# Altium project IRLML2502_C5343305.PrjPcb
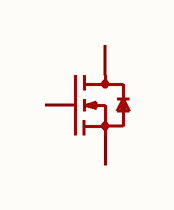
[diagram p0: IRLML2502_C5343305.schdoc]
1 sheet, 1 parts. Net scope: global (net labels, ports and power ports of the same name join across sheets).

## Sheet IRLML2502_C5343305.schdoc
size 127 x 101 mm

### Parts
Q?  irlml2502_c5343305  [SOT-23-3_L2.9-W1.3-P1.90-LS2.4-BR]  (value not drawn)

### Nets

Not connected (* = marked no-connect by the designer): Q? 1(G) 2(S) 3(D)

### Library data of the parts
Q? = irlml2502_c5343305: 数量:1个N沟道;漏源电压(Vdss):20V;连续漏极电流(Id):4A;导通电阻(RDS(on)):30mΩ@4.5V;耗散功率(Pd):1.56W;阈值电压(Vgs(th)):600mV;; Manufacturer: MSKSEMI(美森科); AddInBom: yes; ModelId: c62791f0466c4ae2a892c056b845b0ca; ModelName: SOT-23-3P_L2.9-W1.3-H1.0-LS2.4-P0.95; ModelTransform: 98.425,114.173,0,180,0,0,0.0005,-0.0005,0; Number: 1个N沟道; Drain to Source Voltage: 20V; Current - Continuous Drain(Id): 4A; Pd - Power Dissipation: 1.56W; Gate Threshold Voltage (Vgs(th)): 600mV; Gate Charge(Qg): 5.8nC@4.5V; Input Capacitance(Ciss): 500pF; Reverse Transfer Capacitance (Crss@Vds): 40pF; Type: N沟道; Output Capacitance(Coss): 50pF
